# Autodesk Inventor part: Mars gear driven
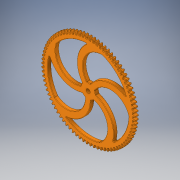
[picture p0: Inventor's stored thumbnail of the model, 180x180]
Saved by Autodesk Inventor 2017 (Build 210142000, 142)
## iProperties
Created: 2016-05
Part Number: Mars gear driven
Material: Generic
Document SubType Name: Modeling
Designer: Stan
Density: 1 g/cm^3
Appearance: Orange
Author: Stan
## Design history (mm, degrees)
sketch "Sketch1"
  geometry: A1 r 23.081 centre (-17.342, -71.813) between (3.92, -80.794) and (5.214, -76.707); A2 r 23.081 centre (28.23, -68.271) between (6.701, -76.591) and (8.611, -80.43); A3 r 23.081 centre (-11.725, -72.941) between (10.169, -80.247) and (11.143, -76.072); A4 r 23.081 centre (33.435, -65.878) between (12.616, -75.842) and (14.818, -79.52); A5 r 23.081 centre (-6.037, -73.63) between (16.357, -79.218) and (17.004, -74.98); A6 r 23.081 centre (38.44, -63.089) between (18.455, -74.636) and (20.936, -78.133); A7 r 23.081 centre (-0.313, -73.876) between (22.447, -77.712) and (22.764, -73.437); A8 r 23.081 centre (43.213, -59.92) between (24.183, -72.981) and (26.927, -76.276); A9 r 23.081 centre (5.413, -73.678) between (28.401, -75.739) and (28.386, -71.452); A10 r 23.081 centre (47.727, -56.391) between (29.766, -70.888) and (32.757, -73.96); A11 r 23.081 centre (11.106, -73.037) between (34.185, -73.311) and (33.838, -69.037); A12 r 23.081 centre (51.953, -52.523) between (35.17, -68.368) and (38.39, -71.199); A13 r 23.081 centre (16.732, -71.957) between (39.763, -70.441) and (39.086, -66.207); A14 r 23.081 centre (55.867, -48.339) between (40.362, -65.437) and (43.792, -68.01); A15 r 23.081 centre (22.258, -70.444) between (45.103, -67.148) and (44.099, -62.98); A16 r 23.081 centre (59.445, -43.865) between (45.312, -62.113) and (48.931, -64.412); A17 r 23.081 centre (27.65, -68.508) between (50.17, -63.451) and (48.847, -59.373); A18 r 23.081 centre (62.665, -39.126) between (49.989, -58.414) and (53.775, -60.426); A19 r 23.081 centre (32.876, -66.159) between (54.936, -59.372) and (53.301, -55.409); A20 r 23.081 centre (65.509, -34.152) between (54.365, -54.365) and (58.296, -56.077); A21 r 23.081 centre (37.904, -63.412) between (59.372, -54.936) and (57.434, -51.112); A22 r 23.081 centre (67.958, -28.973) between (58.414, -49.989) and (62.466, -51.391); A23 r 23.081 centre (42.704, -60.284) between (63.451, -50.17) and (61.222, -46.508); A24 r 23.081 centre (69.999, -23.62) between (62.113, -45.312) and (66.261, -46.396); A25 r 23.081 centre (47.247, -56.794) between (67.148, -45.103) and (64.642, -41.624); A26 r 23.081 centre (71.619, -18.125) between (65.437, -40.362) and (69.657, -41.122); A27 r 23.081 centre (51.506, -52.962) between (70.441, -39.763) and (67.673, -36.489); A28 r 23.081 centre (72.808, -12.52) between (68.368, -35.17) and (72.634, -35.6); A29 r 23.081 centre (55.455, -48.811) between (73.311, -34.185) and (70.297, -31.135); A30 r 23.081 centre (73.56, -6.84) between (70.888, -29.766) and (75.174, -29.865); A31 r 23.081 centre (59.071, -44.367) between (75.739, -28.401) and (72.499, -25.594); A32 r 23.081 centre (73.868, -1.119) between (72.981, -24.183) and (77.262, -23.95); A33 r 23.081 centre (62.331, -39.656) between (77.712, -22.447) and (74.264, -19.899); A34 r 23.081 centre (73.733, 4.608) between (74.636, -18.455) and (78.886, -17.89); A35 r 23.081 centre (65.217, -34.707) between (79.218, -16.357) and (75.583, -14.084); A36 r 23.081 centre (73.154, 10.308) between (75.842, -12.616) and (80.035, -11.723); A37 r 23.081 centre (67.71, -29.548) between (80.247, -10.169) and (76.447, -8.185); A38 r 23.081 centre (72.136, 15.946) between (76.591, -6.701) and (80.703, -5.486); A39 r 23.081 centre (69.797, -24.213) between (80.794, -3.92) and (76.851, -2.236); A40 r 23.081 centre (70.683, 21.488) between (76.88, -0.745) and (80.885, 0.784); A41 r 23.081 centre (71.463, -18.731) between (80.855, 2.353) and (76.794, 3.726); A42 r 23.081 centre (68.805, 26.901) between (76.707, 5.214) and (80.581, 7.05); A43 r 23.081 centre (72.7, -13.137) between (80.43, 8.611) and (76.274, 9.666); A44 r 23.081 centre (66.514, 32.152) between (76.072, 11.143) and (79.793, 13.273); A45 r 23.081 centre (73.499, -7.464) between (79.52, 14.818) and (75.295, 15.547); A46 r 23.081 centre (63.822, 37.209) between (74.98, 17.004) and (78.524, 19.417); A47 r 23.081 centre (73.856, -1.746) between (78.133, 20.936) and (73.864, 21.335); A48 r 23.081 centre (60.747, 42.043) between (73.437, 22.764) and (76.784, 25.443); A49 r 23.081 centre (73.77, 3.983) between (76.276, 26.927) and (71.989, 26.995); A50 r 23.081 centre (57.306, 46.624) between (71.452, 28.386) and (74.581, 31.317); A51 r 23.081 centre (73.239, 9.687) between (73.96, 32.757) and (69.68, 32.493); A52 r 23.081 centre (53.521, 50.925) between (69.037, 33.838) and (71.93, 37.002); A53 r 23.081 centre (72.268, 15.334) between (71.199, 38.39) and (66.953, 37.795); A54 r 23.081 centre (49.414, 54.919) between (66.207, 39.086) and (68.846, 42.465); A55 r 23.081 centre (70.863, 20.888) between (68.01, 43.792) and (63.823, 42.869); A56 r 23.081 centre (45.009, 58.583) between (62.98, 44.099) and (65.348, 47.672); A57 r 23.081 centre (69.031, 26.316) between (64.412, 48.931) and (60.309, 47.686); A58 r 23.081 centre (40.334, 61.895) between (59.373, 48.847) and (61.458, 52.593); A59 r 23.081 centre (66.784, 31.587) between (60.426, 53.775) and (56.432, 52.216); A60 r 23.081 centre (35.416, 64.834) between (55.409, 53.301) and (57.197, 57.197); A61 r 23.081 centre (64.135, 36.667) between (56.077, 58.296) and (52.216, 56.432); A62 r 23.081 centre (30.286, 67.384) between (51.112, 57.434) and (52.593, 61.458); A63 r 23.081 centre (61.101, 41.527) between (51.391, 62.466) and (47.686, 60.309); A64 r 23.081 centre (24.973, 69.528) between (46.508, 61.222) and (47.672, 65.348)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; 1 further point
  constraints: 648 point on circle, 324 centre point, 4 horizontal alignment, 968 other
  dimensions: "d0" = 0 dimension on point (0, 0); "d1" = 0 dimension on point (0, 0)
extrude "Extrusion1" new body sketch "Sketch1" distance "d2" = 6.35; taper "d3" = 0 deg
sketch "Sketch2"
  geometry: C1 r 3.573 at (0, 0); 1 further point
  constraints: 1 centre point, 1 coincident
  dimensions: "d4" = 7.14502 diameter of C1
extrude "Extrusion2" cut sketch "Sketch2" distance "d5" = 6.35; taper "d6" = 0 deg
sketch "Sketch3"
  geometry: A1 r 69.85 centre (0, 0) between (-4.055, 69.732) and (-54.679, 43.466); A2 r 45.341 centre (26.062, 34.027) between (-3.514, 68.394) and (-10.783, 7.601); A3 r 32.798 centre (-23.887, 32.289) between (-54.8, 43.246) and (-13.053, 1.332); A4 r 12.7 centre (0, 0) between (-10.756, 6.752) and (-12.552, 1.936); A5 r 0.762 centre (-4.011, 68.971) between (-3.514, 68.394) and (-4.055, 69.732); A6 r 0.762 centre (-54.082, 42.992) between (-54.679, 43.466) and (-54.8, 43.246); A7 r 0.762 centre (-11.402, 7.157) between (-10.756, 6.752) and (-10.783, 7.601); A8 r 0.762 centre (-13.305, 2.052) between (-13.053, 1.332) and (-12.552, 1.936); A9 r 32.798 centre (-38.09, -12.74) between (-58.064, -38.754) and (-5.301, -12.002); A10 r 12.7 centre (0, 0) between (-9.745, -8.143) and (-5.719, -11.339); A11 r 0.762 centre (-57.6, -38.15) between (-58.235, -38.571) and (-58.064, -38.754); A12 r 0.762 centre (-10.33, -8.632) between (-9.745, -8.143) and (-10.561, -7.906); A13 r 0.762 centre (-6.063, -12.02) between (-5.301, -12.002) and (-5.719, -11.339); A14 r 45.341 centre (-24.308, 35.301) between (-66.132, 17.793) and (-10.561, -7.906); A15 r 69.85 centre (0, 0) between (-67.572, 17.692) and (-58.235, -38.571); A16 r 0.762 centre (-66.835, 17.499) between (-66.132, 17.793) and (-67.572, 17.692); A17 r 32.798 centre (0.346, -40.163) between (18.915, -67.198) and (9.777, -8.75); A18 r 12.7 centre (0, 0) between (4.733, -11.785) and (9.017, -8.944); A19 r 0.762 centre (18.484, -66.57) between (18.687, -67.304) and (18.915, -67.198); A20 r 0.762 centre (5.017, -12.492) between (4.733, -11.785) and (4.255, -12.487); A21 r 0.762 centre (9.558, -9.48) between (9.777, -8.75) and (9.017, -8.944); A22 r 45.341 centre (-41.085, -12.209) between (-37.358, -57.397) and (4.255, -12.487); A23 r 69.85 centre (0, 0) between (-37.707, -58.798) and (18.687, -67.304); A24 r 0.762 centre (-37.295, -58.157) between (-37.358, -57.397) and (-37.707, -58.798); A25 r 32.798 centre (38.304, -12.082) between (69.754, -2.776) and (11.343, 6.594); A26 r 12.7 centre (0, 0) between (12.671, 0.86) and (11.292, 5.812); A27 r 0.762 centre (69.023, -2.992) between (69.784, -3.025) and (69.754, -2.776); A28 r 0.762 centre (13.431, 0.912) between (12.671, 0.86) and (13.191, 0.188); A29 r 0.762 centre (11.97, 6.16) between (11.343, 6.594) and (11.292, 5.812); A30 r 45.341 centre (-1.084, -42.847) between (43.044, -53.266) and (13.191, 0.188); A31 r 69.85 centre (0, 0) between (44.268, -54.031) and (69.784, -3.025); A32 r 0.762 centre (43.785, -53.441) between (43.044, -53.266) and (44.268, -54.031); A33 r 32.798 centre (23.328, 32.696) between (24.195, 65.482) and (-2.766, 12.826); A34 r 12.7 centre (0, 0) between (3.098, 12.316) and (-2.038, 12.535); A35 r 0.762 centre (24.175, 64.72) between (24.442, 65.434) and (24.195, 65.482); A36 r 0.762 centre (3.284, 13.055) between (3.098, 12.316) and (3.897, 12.604); A37 r 0.762 centre (-2.16, 13.288) between (-2.766, 12.826) and (-2.038, 12.535); A38 r 45.341 centre (40.415, -14.272) between (63.961, 24.477) and (3.897, 12.604); A39 r 69.85 centre (0, 0) between (65.066, 25.405) and (24.442, 65.434); A40 r 0.762 centre (64.356, 25.128) between (63.961, 24.477) and (65.066, 25.405); 1 further point
  constraints: 80 point on circle, 40 centre point, 8 tangent, 3 equal radius, 116 other
  dimensions: "d7" = 0 distance of point (0, 0) A1.centre; "d8" = 0 distance of point (0, 0) A1.centre; "d10" = 69.85 radius of A1; "d18" = 12.7 radius of A4; "d22" = 0.762 radius of A5; "d23" = 45.34125 radius of A2; "d24" = 32.79786 radius of A3; "d27" = 360 deg dimension on point (0, 0) A3.centre (derived)
extrude "Extrusion4" cut sketch "Sketch3" distance "d29" = 6.35; taper "d30" = 0 deg
fillet "Fillet1" dims "d31" = 0.762
fillet "Fillet2" dims "d32" = 0.762
fillet "Fillet3" dims "d33" = 0.79375
fillet "Fillet4" dims "d34" = 0.79375
fillet "Fillet5" dims "d35" = 0.79375
fillet "Fillet6" dims "d36" = 0.79375
fillet "Fillet7" dims "d37" = 0.79375
fillet "Fillet8" dims "d38" = 0.79375
fillet "Fillet9" dims "d39" = 0.79375
fillet "Fillet10" dims "d40" = 0.79375
body "Solid1"
other parameters: "d0" = 0, "d1" = 0, "d14" = 28.575
